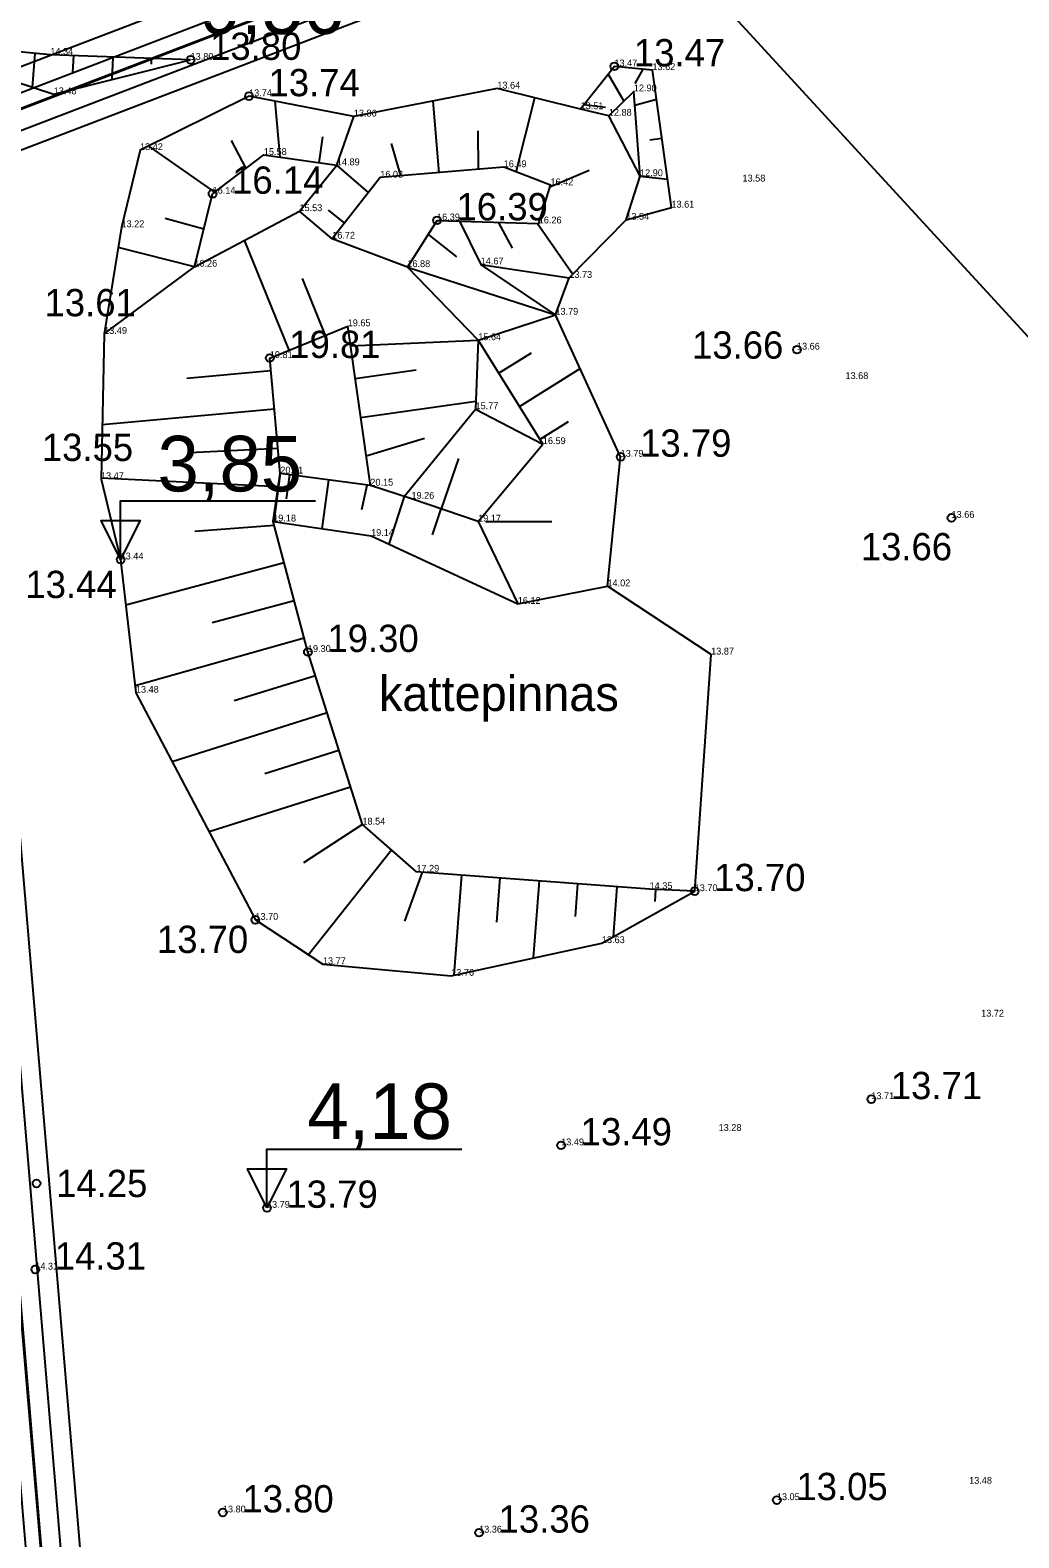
# Model space of a CAD drawing. Extents: x 433497 to 434382, y 6534486 to 6534993.
# Drawn here: x 433622.7 to 433673.4, y 6534719.6 to 6534797 of the extents above; entities that cross this region are included whole.
import ezdxf

# ---------------------------------------------------------------- set-up
doc = ezdxf.new("R2010")
doc.units = 0
for name, color, linetype in [('Default', 7, 'Continuous'), ('GEOLPUNKT', 7, 'Continuous'), ('jääkpaksus', 7, 'Continuous'), ('kataster', 7, 'Continuous'), ('KORGUS-EH2000', 7, 'Continuous'), ('l__x00e4__bil__x00f5__iked', 7, 'Continuous'), ('MOOTKORG-EH2000', 7, 'Continuous'), ('PIIR', 7, 'Continuous'), ('RELJEEF', 7, 'Continuous')]:
    doc.layers.add(name, color=color, linetype=linetype)

msp = doc.modelspace()

# ---------------------------------------------------------------- linework, layer by layer
at = {"layer": 'Default'}
msp.add_lwpolyline([(433617.12, 6534791.025), (433632.75, 6534606.045), (434137.38, 6534796.515), (434127.69, 6534855.6), (433968.21, 6534911.925), (433942.38, 6534904.035), (433920.99, 6534907.275)], close=True, dxfattribs=at)
msp.add_lwpolyline([(433617.12, 6534791.025), (433632.75, 6534606.045), (434137.38, 6534796.515), (434127.69, 6534855.6), (433968.21, 6534911.925), (433942.38, 6534904.035), (433920.99, 6534907.275)], close=True, dxfattribs=at)
msp.add_lwpolyline([(433617.12, 6534791.025), (433632.75, 6534606.045), (434137.38, 6534796.515), (434127.69, 6534855.6), (433968.21, 6534911.925), (433942.38, 6534904.035), (433920.99, 6534907.275)], close=True, dxfattribs=at)
at = {"layer": 'jääkpaksus'}
for points in [[(433627.301, 6534769.827), (433627.301, 6534772.827), (433637.301, 6534772.827)], [(433634.81, 6534736.571), (433634.81, 6534739.571), (433644.81, 6534739.571)]]:
    msp.add_lwpolyline(points, dxfattribs=at)
for points in [[(433627.301, 6534769.827), (433626.301, 6534771.827), (433628.301, 6534771.827)], [(433634.81, 6534736.571), (433633.81, 6534738.571), (433635.81, 6534738.571)]]:
    msp.add_lwpolyline(points, close=True, dxfattribs=at)
at = {"layer": 'kataster'}
msp.add_lwpolyline([(433617.102, 6534791.002), (433632.769, 6534606.029), (434137.446, 6534796.469), (434127.827, 6534855.589), (433950.026, 6534918.39)], close=True, dxfattribs=at)
msp.add_lwpolyline([(433658.341, 6534546.765), (433632.769, 6534606.029), (433617.102, 6534791.002), (433580.107, 6534776.838)], dxfattribs=at)
at = {"layer": 'KORGUS-EH2000'}
for centre in [(433630.892, 6534795.453), (433652.636, 6534795.121), (433633.891, 6534793.589), (433632.02, 6534788.586), (433643.536, 6534787.222), (433662.001, 6534780.591), (433634.955, 6534780.16), (433652.955, 6534775.095), (433669.932, 6534771.96), (433627.301, 6534769.827), (433636.911, 6534765.081), (433656.754, 6534752.814), (433634.216, 6534751.342), (433665.816, 6534742.144), (433649.903, 6534739.775), (433622.99, 6534737.82), (433634.81, 6534736.571), (433622.923, 6534733.403), (433660.97, 6534721.576), (433632.549, 6534720.945), (433645.694, 6534719.91)]:
    msp.add_circle(centre, 0.2, dxfattribs=at)
at = {"layer": 'l__x00e4__bil__x00f5__iked'}
msp.add_lwpolyline([(433633.89, 6534824.093), (433654.744, 6534802.081), (433736.834, 6534712.709), (433742.792, 6534710.723), (433773.907, 6534661.568), (433785.989, 6534638.563)], dxfattribs=at)
at = {"layer": 'PIIR'}
for points in [[(433632.021, 6534604.835), (434138.248, 6534795.936), (434128.468, 6534856.135), (433968.226, 6534912.818), (433942.33, 6534904.85), (433920.952, 6534908.165), (433616.327, 6534791.524), (433632.021, 6534604.835)], [(433632.732, 6534605.959), (434137.353, 6534796.454), (434127.754, 6534855.539), (433968.208, 6534911.976), (433942.39, 6534904.031), (433921.04, 6534907.341), (433617.174, 6534790.992), (433632.732, 6534605.959)], [(433616.435, 6534792.923), (433775.118, 6534853.561)]]:
    msp.add_lwpolyline(points, dxfattribs=at)
for points in [[(433618.234, 6534790.327), (433921.149, 6534906.313), (433942.464, 6534903.008), (433968.187, 6534910.923), (434126.862, 6534854.794), (434136.235, 6534797.101), (433633.617, 6534607.362)], [(433619.24, 6534789.695), (433634.52, 6534608.851), (434135.141, 6534797.808), (434125.908, 6534854.108), (433968.165, 6534909.82), (433942.53, 6534901.99), (433921.212, 6534905.219)], [(433619.24, 6534789.695), (433634.52, 6534608.851), (434135.141, 6534797.808), (434125.908, 6534854.108), (433968.165, 6534909.82), (433942.53, 6534901.99), (433921.212, 6534905.219)]]:
    msp.add_lwpolyline(points, close=True, dxfattribs=at)
at = {"layer": 'RELJEEF'}
for p, q in [((433622.9, 6534795.789), (433622.765, 6534794.053)), ((433624.854, 6534794.799), (433624.896, 6534795.67)), ((433626.895, 6534795.597), (433626.853, 6534794.44)), ((433628.883, 6534795.236), (433628.893, 6534795.525)), ((433630.892, 6534795.453), (433630.892, 6534795.453)), ((433652.314, 6534794.713), (433653.112, 6534793.331)), ((433653.707, 6534794.248), (433654.109, 6534794.976)), ((433635.489, 6534790.458), (433635.234, 6534793.329)), ((433643.65, 6534789.668), (433643.339, 6534793.34)), ((433647.592, 6534789.703), (433648.552, 6534793.503)), ((433652.178, 6534793.013), (433651.074, 6534793.144)), ((433654.796, 6534793.425), (433653.686, 6534793.109)), ((433645.627, 6534791.809), (433645.643, 6534789.837)), ((433632.136, 6534788.673), (433628.729, 6534791.039)), ((433632.975, 6534791.322), (433633.73, 6534789.88)), ((433637.656, 6534791.501), (433637.469, 6534790.178)), ((433641.177, 6534791.163), (433641.657, 6534789.5)), ((433654.445, 6534791.357), (433655.069, 6534791.444)), ((433640.027, 6534788.657), (433638.396, 6534790.047)), ((433651.335, 6534789.787), (433649.324, 6534788.917)), ((433653.95, 6534789.488), (433655.36, 6534789.338)), ((433637.944, 6534787.752), (433638.79, 6534787.085)), ((433629.58, 6534787.333), (433631.57, 6534786.786)), ((433644.694, 6534787.187), (433645.777, 6534784.961)), ((433647.408, 6534785.795), (433646.693, 6534787.127)), ((433648.692, 6534787.067), (433650.502, 6534784.455)), ((433635.953, 6534780.567), (433633.653, 6534786.203)), ((433644.547, 6534785.359), (433643.085, 6534786.511)), ((433631.085, 6534784.846), (433627.176, 6534785.823)), ((433642.013, 6534784.823), (433649.609, 6534782.382)), ((433636.617, 6534784.232), (433637.804, 6534781.323)), ((433645.65, 6534781.076), (433649.609, 6534782.382)), ((433639.094, 6534780.789), (433645.65, 6534781.076)), ((433648.372, 6534780.413), (433646.706, 6534779.377)), ((433630.707, 6534779.133), (433635.013, 6534779.526)), ((433642.471, 6534779.538), (433639.335, 6534779.092)), ((433647.762, 6534777.679), (433650.879, 6534779.616)), ((433639.617, 6534777.112), (433645.527, 6534777.953)), ((433635.195, 6534777.534), (433626.356, 6534776.727)), ((433641.856, 6534773.056), (433645.51, 6534777.535)), ((433650.269, 6534776.882), (433648.817, 6534775.98)), ((433630.849, 6534775.316), (433635.377, 6534775.543)), ((433642.89, 6534776.034), (433639.898, 6534775.132)), ((433645.643, 6534771.769), (433648.964, 6534775.744)), ((433644.632, 6534775.008), (433643.751, 6534772.416)), ((433635.395, 6534773.556), (433626.297, 6534774.006)), ((433635.496, 6534774.235), (433635.166, 6534771.771)), ((433635.815, 6534772.935), (433635.981, 6534774.17)), ((433637.963, 6534773.904), (433637.628, 6534771.407)), ((433639.673, 6534772.392), (433639.945, 6534773.639)), ((433641.856, 6534773.056), (433641.07, 6534770.609)), ((433643.303, 6534771.099), (433643.751, 6534772.416)), ((433631.103, 6534771.271), (433635.181, 6534771.582)), ((433645.643, 6534771.769), (433647.677, 6534767.549)), ((433646.032, 6534771.772), (433649.422, 6534771.772)), ((433635.695, 6534769.649), (433627.57, 6534767.487)), ((433632.005, 6534766.598), (433636.209, 6534767.717)), ((433636.724, 6534765.784), (433628.047, 6534763.339)), ((433633.132, 6534762.591), (433637.294, 6534763.867)), ((433637.896, 6534761.96), (433629.95, 6534759.451)), ((433634.697, 6534758.853), (433638.499, 6534760.053)), ((433639.101, 6534758.146), (433631.842, 6534755.854)), ((433636.702, 6534754.28), (433639.703, 6534756.239)), ((433641.205, 6534754.921), (433636.946, 6534749.549)), ((433641.879, 6534751.279), (433642.789, 6534753.789)), ((433644.783, 6534753.64), (433644.399, 6534748.501)), ((433646.608, 6534751.217), (433646.778, 6534753.491)), ((433648.772, 6534753.342), (433648.476, 6534749.385)), ((433650.641, 6534751.51), (433650.767, 6534753.193)), ((433652.761, 6534753.043), (433652.575, 6534750.473)), ((433654.72, 6534752.279), (433654.756, 6534752.904)), ((433656.754, 6534752.814), (433656.754, 6534752.814))]:
    msp.add_line(p, q, dxfattribs=at)
for points in [[(433630.892, 6534795.453), (433623.697, 6534795.713), (433617.372, 6534796.319), (433610.285, 6534794.703), (433605.139, 6534793.405), (433599.373, 6534794.656)], [(433599.373, 6534794.656), (433603.668, 6534792.439), (433607.913, 6534792.835), (433612.854, 6534794.534), (433618.799, 6534795.352), (433623.869, 6534793.691), (433630.892, 6534795.453)], [(433653.246, 6534787.252), (433655.562, 6534787.876), (433654.588, 6534794.929), (433652.636, 6534795.121), (433650.899, 6534792.923)], [(433656.754, 6534752.814), (433657.599, 6534764.951), (433652.281, 6534768.45), (433652.955, 6534775.095), (433649.609, 6534782.382), (433650.321, 6534784.271), (433653.246, 6534787.252), (433653.95, 6534789.488), (433652.35, 6534792.588), (433650.899, 6534792.923), (433646.628, 6534793.979), (433639.267, 6534792.549), (433633.891, 6534793.589), (433628.299, 6534790.827), (433627.346, 6534786.868), (433626.458, 6534781.4), (433626.296, 6534773.949), (433627.301, 6534769.827), (433628.087, 6534762.992), (433634.216, 6534751.342), (433637.683, 6534749.065), (433644.264, 6534748.472), (433651.995, 6534750.148), (433656.754, 6534752.814)], [(433653.95, 6534789.488), (433653.633, 6534793.84), (433652.35, 6534792.588)], [(433626.458, 6534781.4), (433631.085, 6534784.846), (433636.477, 6534787.695), (433638.396, 6534790.047), (433639.267, 6534792.549)], [(433631.085, 6534784.846), (433632.02, 6534788.586), (433634.65, 6534790.576), (433638.396, 6534790.047)], [(433642.013, 6534784.823), (433643.536, 6534787.222), (433648.754, 6534787.065), (433649.356, 6534789.022), (433646.957, 6534789.948), (433640.622, 6534789.412), (433638.157, 6534786.282)], [(433642.013, 6534784.823), (433638.157, 6534786.282), (433636.477, 6534787.695)], [(433642.013, 6534784.823), (433645.65, 6534781.076), (433645.51, 6534777.535), (433648.964, 6534775.744)], [(433649.609, 6534782.382), (433645.777, 6534784.961), (433650.321, 6534784.271)], [(433656.754, 6534752.814), (433654.44, 6534752.918), (433642.478, 6534753.812), (433639.707, 6534756.226), (433636.911, 6534765.081), (433635.129, 6534771.776), (433635.496, 6534774.235), (433634.955, 6534780.16), (433638.951, 6534781.791)], [(433640.114, 6534773.616), (433638.951, 6534781.791)], [(433645.65, 6534781.076), (433648.964, 6534775.744)], [(433645.643, 6534771.769), (433642.223, 6534772.938), (433640.114, 6534773.616), (433635.496, 6534774.235)], [(433635.129, 6534771.776), (433640.153, 6534771.034), (433647.677, 6534767.549), (433652.281, 6534768.45)]]:
    msp.add_lwpolyline(points, dxfattribs=at)

# ---------------------------------------------------------------- texts
at = {"layer": 'GEOLPUNKT'}
msp.add_text('9,56*', height=2.85, dxfattribs=at).set_placement((433631.366, 6534796.785))
at = {"layer": 'jääkpaksus'}
for s, p in [(' 3,85', (433628.138, 6534773.319)), (' 4,18', (433635.825, 6534740.098))]:
    msp.add_text(s, height=2.85, rotation=360, dxfattribs=at).set_placement(p)
at = {"layer": 'KORGUS-EH2000'}
for s, p in [('13.80', (433631.892, 6534795.453)), ('13.47', (433653.636, 6534795.121)), ('13.74', (433634.891, 6534793.589)), ('16.14', (433633.02, 6534788.586)), ('16.39', (433644.536, 6534787.222)), ('13.61', (433623.398, 6534782.302)), ('19.81', (433635.955, 6534780.16)), ('13.66', (433656.618, 6534780.127)), ('13.55', (433623.259, 6534774.878)), ('13.79', (433653.955, 6534775.095)), ('13.66', (433665.275, 6534769.784)), ('13.44', (433622.416, 6534767.847)), ('19.30', (433637.911, 6534765.081)), ('13.70', (433657.754, 6534752.814)), ('13.70', (433629.165, 6534749.643)), ('13.71', (433666.816, 6534742.144)), ('13.49', (433650.903, 6534739.775)), ('14.25', (433623.99, 6534737.12)), ('13.79', (433635.81, 6534736.571)), ('14.31', (433623.923, 6534733.403)), ('13.05', (433661.97, 6534721.576)), ('13.80', (433633.549, 6534720.945)), ('13.36', (433646.694, 6534719.91))]:
    msp.add_text(s, height=1.4, dxfattribs=at).set_placement(p)
at = {"layer": 'MOOTKORG-EH2000'}
for s, p in [('14.34', (433623.697, 6534795.713)), ('13.80', (433630.892, 6534795.453)), ('13.47', (433652.636, 6534795.121)), ('13.62', (433654.588, 6534794.929)), ('13.48', (433623.869, 6534793.691)), ('13.74', (433633.891, 6534793.589)), ('13.64', (433646.628, 6534793.979)), ('12.90', (433653.633, 6534793.84)), ('13.51', (433650.899, 6534792.923)), ('13.86', (433639.267, 6534792.549)), ('12.88', (433652.35, 6534792.588)), ('13.42', (433628.299, 6534790.827)), ('15.58', (433634.65, 6534790.576)), ('14.89', (433638.396, 6534790.047)), ('16.49', (433646.957, 6534789.948)), ('16.03', (433640.622, 6534789.412)), ('16.42', (433649.356, 6534789.022)), ('12.90', (433653.95, 6534789.488)), ('13.58', (433659.207, 6534789.213)), ('16.14', (433632.02, 6534788.586)), ('15.53', (433636.477, 6534787.695)), ('13.61', (433655.562, 6534787.876)), ('13.22', (433627.346, 6534786.868)), ('16.39', (433643.536, 6534787.222)), ('16.26', (433648.754, 6534787.065)), ('13.54', (433653.246, 6534787.252)), ('16.72', (433638.157, 6534786.282)), ('16.26', (433631.085, 6534784.846)), ('16.88', (433642.013, 6534784.823)), ('14.67', (433645.777, 6534784.961)), ('13.73', (433650.321, 6534784.271)), ('13.79', (433649.609, 6534782.382)), ('13.49', (433626.458, 6534781.4)), ('19.65', (433638.951, 6534781.791)), ('15.64', (433645.65, 6534781.076)), ('13.66', (433662.001, 6534780.591)), ('19.81', (433634.955, 6534780.16)), ('13.68', (433664.491, 6534779.081)), ('15.77', (433645.51, 6534777.535)), ('16.59', (433648.964, 6534775.744)), ('13.79', (433652.955, 6534775.095)), ('20.41', (433635.496, 6534774.235)), ('13.47', (433626.296, 6534773.949)), ('20.15', (433640.114, 6534773.616)), ('19.26', (433642.223, 6534772.938)), ('13.66', (433669.932, 6534771.96)), ('19.18', (433635.129, 6534771.776)), ('19.17', (433645.643, 6534771.769)), ('19.14', (433640.153, 6534771.034)), ('13.44', (433627.301, 6534769.827)), ('14.02', (433652.281, 6534768.45)), ('16.12', (433647.677, 6534767.549)), ('19.30', (433636.911, 6534765.081)), ('13.87', (433657.599, 6534764.951)), ('13.48', (433628.087, 6534762.992)), ('18.54', (433639.707, 6534756.226)), ('17.29', (433642.478, 6534753.812)), ('14.35', (433654.44, 6534752.918)), ('13.70', (433656.754, 6534752.814)), ('13.70', (433634.216, 6534751.342)), ('13.63', (433651.995, 6534750.148)), ('13.77', (433637.683, 6534749.065)), ('13.76', (433644.264, 6534748.472)), ('13.72', (433671.451, 6534746.379)), ('13.71', (433665.816, 6534742.144)), ('13.28', (433657.982, 6534740.513)), ('13.49', (433649.903, 6534739.775)), ('13.79', (433634.81, 6534736.571)), ('14.31', (433622.923, 6534733.403)), ('13.48', (433670.835, 6534722.417)), ('13.80', (433632.549, 6534720.945)), ('13.05', (433660.97, 6534721.576)), ('13.36', (433645.694, 6534719.91))]:
    msp.add_text(s, height=0.35, dxfattribs=at).set_placement(p)
at = {"layer": 'RELJEEF'}
msp.add_text('kattepinnas', height=1.8, dxfattribs=at).set_placement((433640.553, 6534762.054))

doc.saveas('drawing.dxf')
